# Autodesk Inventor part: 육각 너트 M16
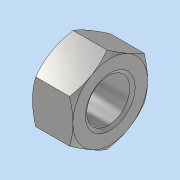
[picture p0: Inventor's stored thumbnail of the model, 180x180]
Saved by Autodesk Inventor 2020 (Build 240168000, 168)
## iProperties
Created: 2025-01
Part Number: 육각 너트 M16
Material: 강철, 연강
Description: 6각 너트
Document SubType Name: Modeling
Designer: 1강의실14
Density: 7.85 g/cm^3
Appearance: 기본값
Author: jhkim
Sending System: Autodesk Inventor 2025
Preprocessor: ST-DEVELOPER v20
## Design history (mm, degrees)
feature "Solid1"
node "솔리드1"
